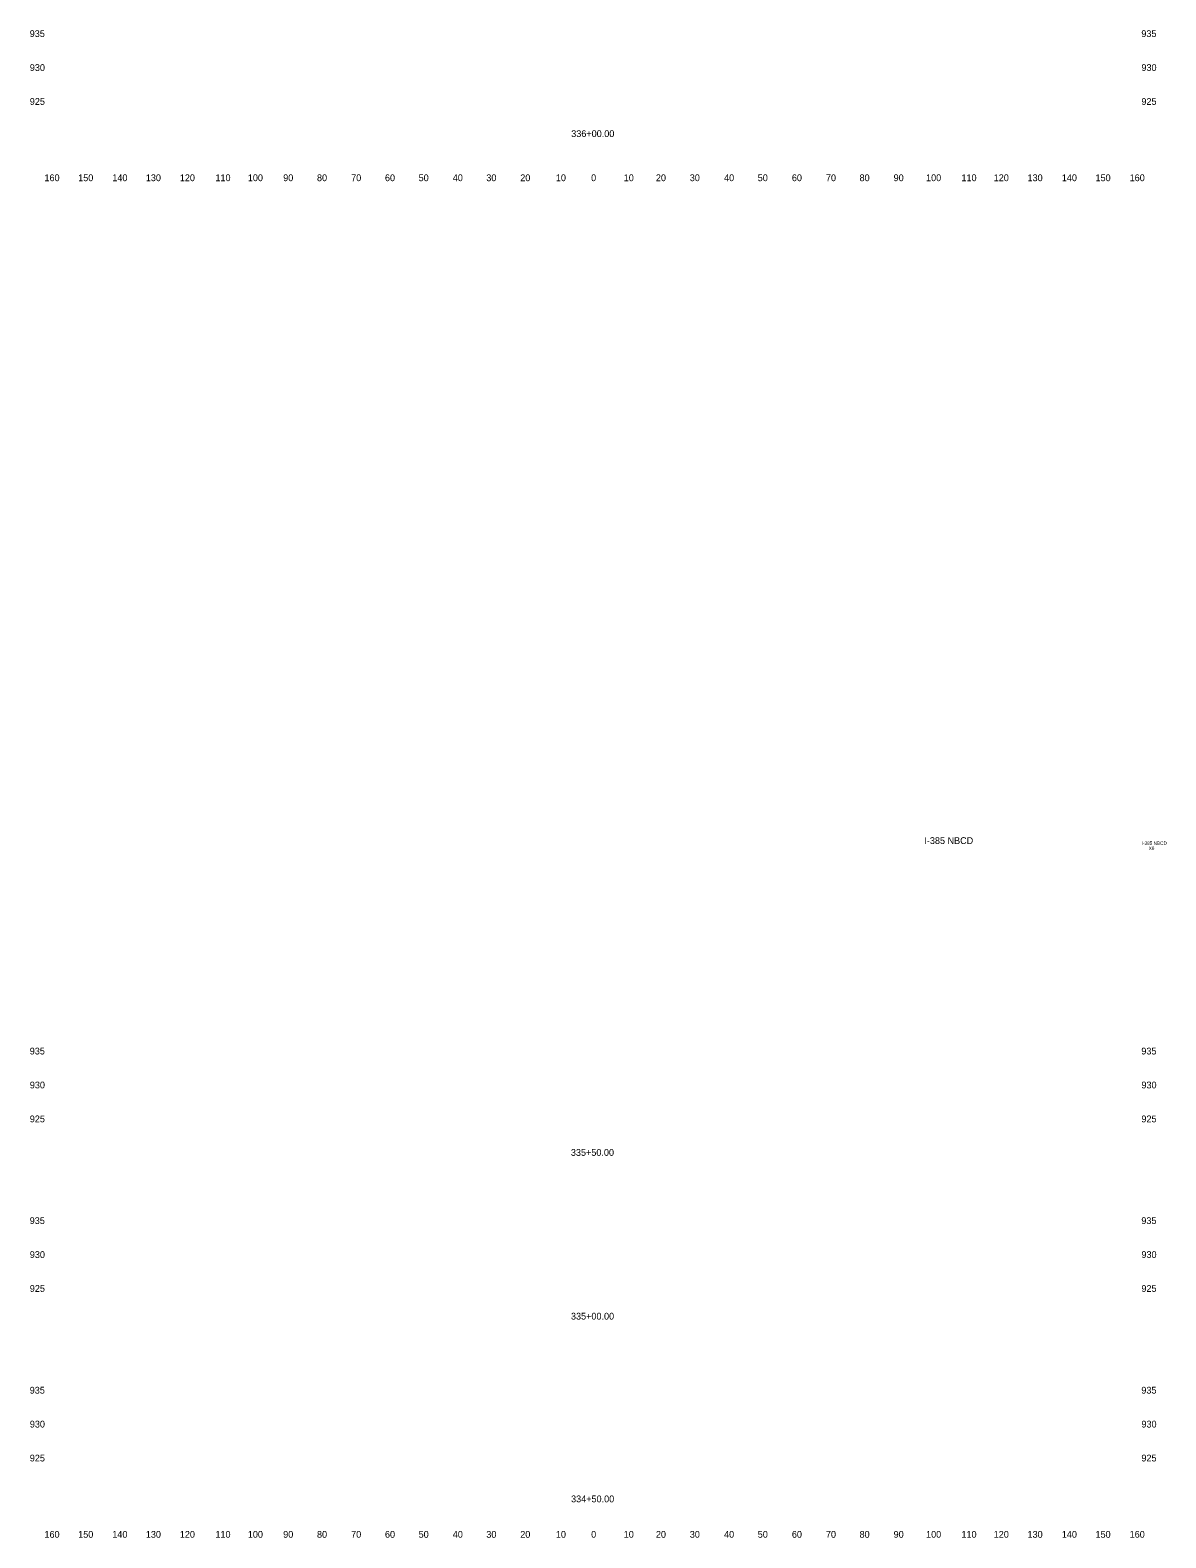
# Model space of a CAD drawing. Extents: x 4994 to 7391, y 4997 to 8804.
# Drawn here: x 4993.9 to 5328.8, y 6997.5 to 7442 of the extents above; entities that cross this region are included whole.
import ezdxf

# ---------------------------------------------------------------- set-up
doc = ezdxf.new("R2010")
doc.units = 0
for name, color, linetype in [('RD_SHT_ID', 7, 'Continuous'), ('RD_XS_TX_Offset', 7, 'Continuous'), ('RD_XS_TX_Station', 7, 'Continuous')]:
    doc.layers.add(name, color=color, linetype=linetype)

msp = doc.modelspace()

# ---------------------------------------------------------------- texts
at = {"layer": 'RD_SHT_ID'}
for s, height, p in [('I-385 NBCD', 2, (5257.56, 7202.06)), ('I-385 NBCD', 1, (5321.63, 7201.8)), ('X6', 1, (5323.71, 7200.3))]:
    msp.add_text(s, height=height, dxfattribs=at).set_placement(p)
at = {"layer": 'RD_XS_TX_Offset'}
for s, p in [('935', (4993.75, 7440)), ('935', (5321.55, 7440)), ('930', (4993.78, 7430)), ('930', (5321.58, 7430)), ('925', (4993.77, 7420)), ('925', (5321.57, 7420)), ('160', (4998.1, 7397.5)), ('150', (5008.04, 7397.5)), ('140', (5018.1, 7397.5)), ('130', (5027.99, 7397.5)), ('120', (5038.01, 7397.5)), ('110', (5048.51, 7397.5)), ('100', (5058.07, 7397.5)), ('90', (5068.5, 7397.5)), ('80', (5078.46, 7397.5)), ('70', (5088.54, 7397.5)), ('60', (5098.5, 7397.5)), ('50', (5108.43, 7397.5)), ('40', (5118.5, 7397.5)), ('30', (5128.39, 7397.5)), ('20', (5138.4, 7397.5)), ('10', (5148.91, 7397.5)), ('0', (5159.3, 7397.5)), ('0', (5159.3, 7397.5)), ('10', (5168.91, 7397.5)), ('20', (5178.4, 7397.5)), ('30', (5188.39, 7397.5)), ('40', (5198.5, 7397.5)), ('50', (5208.43, 7397.5)), ('60', (5218.5, 7397.5)), ('70', (5228.54, 7397.5)), ('80', (5238.46, 7397.5)), ('90', (5248.5, 7397.5)), ('100', (5258.07, 7397.5)), ('110', (5268.51, 7397.5)), ('120', (5278.01, 7397.5)), ('130', (5287.99, 7397.5)), ('140', (5298.1, 7397.5)), ('150', (5308.04, 7397.5)), ('160', (5318.1, 7397.5)), ('935', (4993.75, 7140)), ('935', (5321.55, 7140)), ('930', (4993.78, 7130)), ('930', (5321.58, 7130)), ('925', (4993.77, 7120)), ('925', (5321.57, 7120)), ('935', (4993.75, 7090)), ('935', (5321.55, 7090)), ('930', (4993.78, 7080)), ('930', (5321.58, 7080)), ('925', (4993.77, 7070)), ('925', (5321.57, 7070)), ('935', (4993.75, 7040)), ('935', (5321.55, 7040)), ('930', (4993.78, 7030)), ('930', (5321.58, 7030)), ('925', (4993.77, 7020)), ('925', (5321.57, 7020)), ('160', (4998.1, 6997.5)), ('150', (5008.04, 6997.5)), ('140', (5018.1, 6997.5)), ('130', (5027.99, 6997.5)), ('120', (5038.01, 6997.5)), ('110', (5048.51, 6997.5)), ('100', (5058.07, 6997.5)), ('90', (5068.5, 6997.5)), ('80', (5078.46, 6997.5)), ('70', (5088.54, 6997.5)), ('60', (5098.5, 6997.5)), ('50', (5108.43, 6997.5)), ('40', (5118.5, 6997.5)), ('30', (5128.39, 6997.5)), ('20', (5138.4, 6997.5)), ('10', (5148.91, 6997.5)), ('0', (5159.3, 6997.5)), ('0', (5159.3, 6997.5)), ('10', (5168.91, 6997.5)), ('20', (5178.4, 6997.5)), ('30', (5188.39, 6997.5)), ('40', (5198.5, 6997.5)), ('50', (5208.43, 6997.5)), ('60', (5218.5, 6997.5)), ('70', (5228.54, 6997.5)), ('80', (5238.46, 6997.5)), ('90', (5248.5, 6997.5)), ('100', (5258.07, 6997.5)), ('110', (5268.51, 6997.5)), ('120', (5278.01, 6997.5)), ('130', (5287.99, 6997.5)), ('140', (5298.1, 6997.5)), ('150', (5308.04, 6997.5)), ('160', (5318.1, 6997.5))]:
    msp.add_text(s, height=2, dxfattribs=at).set_placement(p)
at = {"layer": 'RD_XS_TX_Station'}
for s, p in [('336+00.00', (5153.43, 7410.51)), ('335+50.00', (5153.33, 7110.11)), ('335+00.00', (5153.36, 7061.83)), ('334+50.00', (5153.39, 7007.96))]:
    msp.add_text(s, height=2, dxfattribs=at).set_placement(p)

doc.saveas('drawing.dxf')
